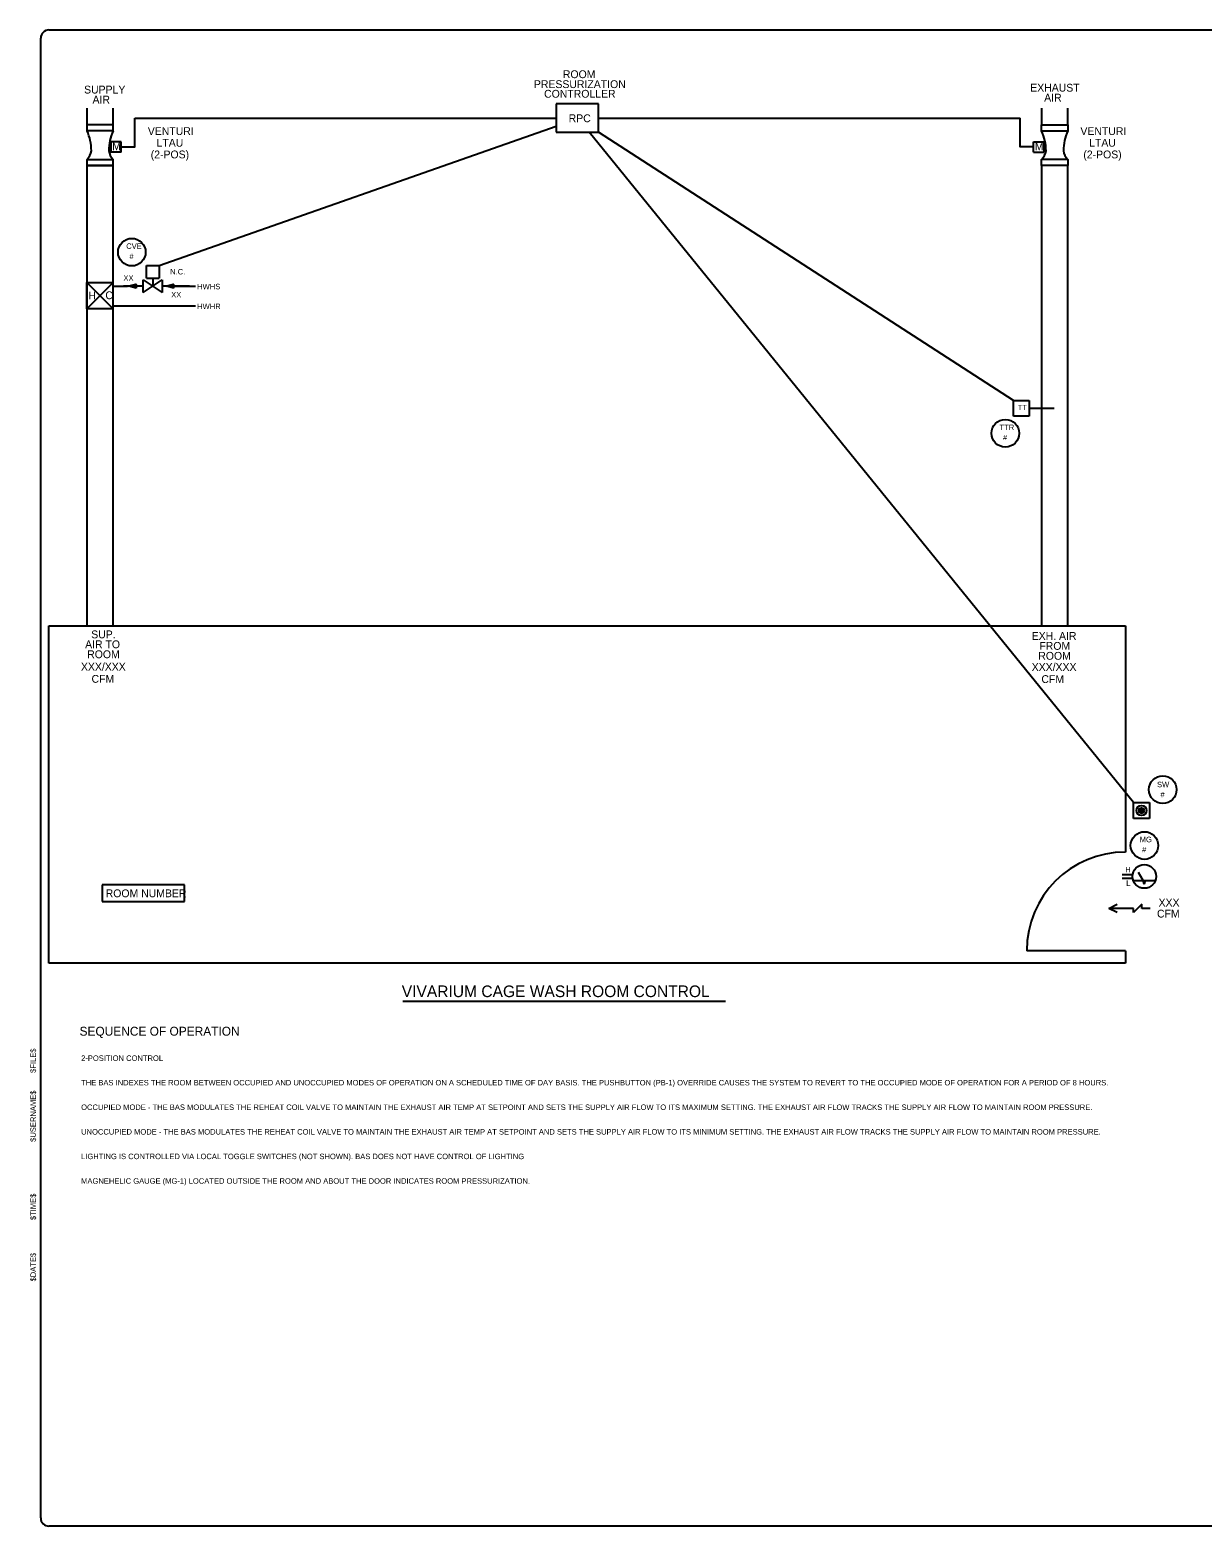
# Model space of a CAD drawing. Extents: x 0 to 567, y 1 to 184.
# Drawn here: x 289.6 to 432.3, y 1.7 to 183.7 of the extents above; entities that cross this region are included whole.
import ezdxf

# ---------------------------------------------------------------- set-up
doc = ezdxf.new("R2010")
doc.units = 0
for name, color, linetype in [('Default', 7, 'Continuous'), ('G-ANNO-CELL', 7, 'Continuous'), ('G-ANNO-NODE', 7, 'Continuous'), ('G-ANNO-TEXT', 7, 'Continuous'), ('G-ANNO-TTLB', 7, 'Continuous'), ('G-DETL-LINE', 7, 'Continuous'), ('G-DETL-TEXT', 7, 'Continuous')]:
    doc.layers.add(name, color=color, linetype=linetype)

msp = doc.modelspace()

# ---------------------------------------------------------------- linework, layer by layer
at = {"layer": 'G-ANNO-CELL'}
msp.add_line((334.98, 65.6), (374.27, 65.6), dxfattribs=at)
at = {"layer": 'G-ANNO-TTLB'}
for points in [[(290.92, 2.73), (290.92, 182.73)], [(291.92, 183.73), (535.67, 183.73)], [(535.67, 1.73), (291.92, 1.73)]]:
    msp.add_lwpolyline(points, dxfattribs=at)
for centre, start, end in [((291.92, 182.73), 90, 180), ((291.92, 2.73), 180, 270.0001)]:
    msp.add_arc(centre, 1, start, end, dxfattribs=at)
at = {"layer": 'G-DETL-LINE'}
for p, q in [((353.63, 174.74), (353.63, 171.28)), ((358.81, 174.74), (353.63, 174.74)), ((358.81, 171.28), (358.81, 174.74)), ((296.55, 174.23), (296.55, 172.17)), ((299.75, 172.17), (299.75, 174.23)), ((302.36, 173.01), (353.63, 173.01)), ((358.81, 173.01), (410.12, 173.01)), ((412.72, 174.23), (412.72, 172.17)), ((415.92, 172.17), (415.92, 174.23)), ((299.75, 171.44), (296.55, 171.44)), ((305.33, 155.06), (353.63, 172.03)), ((353.63, 171.28), (358.81, 171.28)), ((423.92, 89.74), (357.66, 171.28)), ((409.31, 138.65), (358.81, 171.28)), ((412.72, 171.44), (415.92, 171.44)), ((299.46, 170.14), (299.46, 168.86)), ((300.73, 170.14), (299.46, 170.14)), ((300.73, 168.86), (300.73, 170.14)), ((411.74, 170.14), (413.01, 170.14)), ((411.74, 168.86), (411.74, 170.14)), ((413.01, 170.14), (413.01, 168.86)), ((296.55, 167.98), (299.75, 167.98)), ((415.92, 167.98), (412.72, 167.98)), ((296.55, 167.24), (296.55, 111.23)), ((299.75, 167.24), (296.55, 167.24)), ((299.75, 111.23), (299.75, 167.24)), ((412.72, 167.24), (412.72, 111.23)), ((415.92, 111.23), (415.92, 167.24)), ((303.79, 153.52), (303.79, 155.06)), ((303.79, 155.06), (305.33, 155.06)), ((305.33, 155.06), (305.33, 153.52)), ((296.55, 149.8), (296.55, 153)), ((296.55, 153), (299.75, 153)), ((296.55, 153), (299.75, 149.8)), ((296.55, 149.8), (299.75, 153)), ((299.75, 149.8), (299.75, 153)), ((303.41, 151.79), (303.41, 153.33)), ((303.41, 153.33), (305.71, 151.79)), ((303.41, 151.79), (305.71, 153.33)), ((303.79, 153.52), (305.33, 153.52)), ((304.56, 153.52), (304.56, 152.56)), ((305.71, 153.33), (305.71, 151.79)), ((299.75, 152.56), (301.49, 152.56)), ((303.41, 152.56), (301, 152.56)), ((302.55, 152.56), (301.65, 152.56)), ((302.55, 152.6), (301.82, 152.6)), ((302.55, 152.52), (301.82, 152.52)), ((302.55, 152.64), (301.99, 152.64)), ((302.55, 152.48), (301.99, 152.48)), ((302.55, 152.68), (302.15, 152.68)), ((302.55, 152.44), (302.15, 152.44)), ((302.55, 152.72), (302.31, 152.72)), ((302.55, 152.4), (302.31, 152.4)), ((302.55, 152.76), (302.45, 152.76)), ((302.55, 152.36), (302.45, 152.36)), ((309.01, 152.56), (305.71, 152.56)), ((307.1, 152.56), (306.21, 152.56)), ((307.1, 152.6), (306.38, 152.6)), ((307.1, 152.52), (306.38, 152.52)), ((307.1, 152.64), (306.54, 152.64)), ((307.1, 152.48), (306.54, 152.48)), ((307.1, 152.68), (306.7, 152.68)), ((307.1, 152.44), (306.7, 152.44)), ((306.85, 152.56), (309.76, 152.56)), ((307.1, 152.72), (306.86, 152.72)), ((307.1, 152.4), (306.86, 152.4)), ((307.1, 152.76), (307.01, 152.76)), ((307.1, 152.36), (307.01, 152.36)), ((299.75, 149.8), (296.55, 149.8)), ((299.75, 150.16), (309.76, 150.16)), ((409.31, 138.65), (411.23, 138.65)), ((409.31, 136.73), (409.31, 138.65)), ((411.23, 138.65), (411.23, 136.73)), ((411.23, 136.73), (409.31, 136.73)), ((414.24, 137.69), (411.23, 137.69)), ((291.92, 111.23), (422.92, 111.23)), ((291.92, 70.23), (291.92, 111.23)), ((422.92, 111.23), (422.92, 83.73)), ((423.92, 89.74), (425.84, 89.74)), ((423.92, 87.82), (423.92, 89.74)), ((425.84, 89.74), (425.84, 87.82)), ((425.84, 87.82), (423.92, 87.82)), ((424.56, 88.72), (424.94, 89.1)), ((424.56, 88.77), (424.89, 89.1)), ((424.56, 88.83), (424.83, 89.1)), ((424.56, 88.8), (424.91, 88.45)), ((424.56, 88.74), (424.85, 88.45)), ((424.57, 88.85), (424.96, 88.46)), ((424.58, 88.67), (424.99, 89.08)), ((424.58, 88.89), (425, 88.47)), ((424.58, 88.67), (424.78, 88.47)), ((424.59, 88.63), (425.03, 89.07)), ((424.59, 88.91), (424.75, 89.07)), ((424.6, 88.93), (425.04, 88.49)), ((424.61, 88.6), (425.06, 89.05)), ((424.62, 88.97), (425.07, 88.51)), ((424.64, 88.56), (425.1, 89.02)), ((424.65, 89), (425.11, 88.54)), ((424.67, 88.54), (425.12, 88.99)), ((424.68, 89.02), (425.13, 88.57)), ((424.7, 88.51), (425.15, 88.96)), ((424.71, 89.05), (425.16, 88.6)), ((424.73, 88.49), (425.17, 88.93)), ((424.74, 89.07), (425.18, 88.63)), ((424.77, 88.47), (425.19, 88.89)), ((424.78, 89.08), (425.19, 88.68)), ((424.81, 88.46), (425.2, 88.85)), ((424.83, 89.1), (425.21, 88.72)), ((424.86, 88.45), (425.21, 88.8)), ((424.88, 89.1), (425.21, 88.77)), ((424.92, 88.45), (425.21, 88.74)), ((424.94, 89.1), (425.2, 88.83)), ((425, 88.47), (425.19, 88.66)), ((425.03, 89.07), (425.18, 88.92)), ((422.51, 81.01), (423.8, 81.01)), ((422.52, 80.53), (423.78, 80.53)), ((423.86, 80.28), (426.58, 80.28)), ((425.08, 80.28), (424.5, 81.24)), ((298.42, 79.73), (298.42, 77.73)), ((308.42, 79.73), (298.42, 79.73)), ((308.42, 77.73), (308.42, 79.73)), ((425.22, 80.04), (425.1, 80.04)), ((425.34, 80.04), (425.22, 80.04)), ((298.42, 77.73), (308.42, 77.73)), ((420.92, 76.88), (421.92, 77.38)), ((423.92, 76.88), (420.92, 76.88)), ((421.92, 76.38), (420.92, 76.88)), ((424.92, 77.38), (423.92, 76.38)), ((423.92, 76.38), (423.92, 76.88)), ((424.92, 76.88), (424.92, 77.38)), ((425.92, 76.88), (424.92, 76.88)), ((422.92, 71.73), (410.92, 71.73)), ((422.92, 71.73), (422.92, 70.23)), ((422.92, 70.23), (291.92, 70.23))]:
    msp.add_line(p, q, dxfattribs=at)
for points in [[(300.73, 169.5), (302.36, 169.5), (302.36, 173.01)], [(411.74, 169.5), (410.12, 169.5), (410.12, 173.01)], [(299.75, 171.44), (299.75, 172.17), (296.55, 172.17), (296.55, 171.44)], [(412.72, 171.44), (412.72, 172.17), (415.92, 172.17), (415.92, 171.44)], [(296.55, 167.98), (296.55, 167.24), (299.75, 167.24), (299.75, 167.98)], [(300.73, 168.86), (299.46, 168.86)], [(411.74, 168.86), (413.01, 168.86)], [(415.92, 167.98), (415.92, 167.24), (412.72, 167.24), (412.72, 167.98)], [(302.55, 152.33), (301.65, 152.56), (302.55, 152.78), (302.55, 152.33)], [(307.1, 152.33), (306.21, 152.56), (307.1, 152.78), (307.1, 152.33)]]:
    msp.add_lwpolyline(points, dxfattribs=at)
for centre, radius in [((424.88, 88.78), 0.617), ((424.88, 88.78), 0.325), ((425.22, 80.76), 1.44)]:
    msp.add_circle(centre, radius, dxfattribs=at)
for centre, radius, start, end in [((291.42, 169.04), 5.67, 0, 25.0576), ((304.88, 169.04), 5.67, 154.9424, 180), ((407.59, 169.04), 5.67, 0, 25.0576), ((421.05, 169.04), 5.67, 154.9424, 180), ((295.22, 169.31), 1.89, 315, 351.8699), ((301.08, 169.31), 1.89, 188.1301, 225), ((411.39, 169.31), 1.89, 315, 351.8699), ((417.25, 169.31), 1.89, 188.1301, 225), ((422.92, 71.73), 12, 90, 180), ((425.22, 80.04), 0.12, 0, 180), ((425.22, 80.04), 0.12, 180, 0)]:
    msp.add_arc(centre, radius, start, end, dxfattribs=at)
at = {"layer": 'G-DETL-TEXT'}
for centre in [(302.01, 156.7), (408.31, 134.67), (427.47, 91.32), (425.24, 84.52)]:
    msp.add_circle(centre, 1.68, dxfattribs=at)

# ---------------------------------------------------------------- texts
at = {"layer": 'Default'}
for s, p in [('TT', (409.83, 137.48)), ('#', (408.04, 133.84))]:
    msp.add_text(s, height=0.64, dxfattribs=at).set_placement(p)
at = {"layer": 'G-ANNO-CELL'}
for s, height, p in [('VIVARIUM CAGE WASH ROOM CONTROL', 1.4167, (334.86, 66.08)), ('SEQUENCE OF OPERATION', 1.0833, (295.65, 61.39))]:
    msp.add_text(s, height=height, dxfattribs=at).set_placement(p)
at = {"layer": 'G-ANNO-NODE'}
for s, p in [('$FILE$', (290.33, 56.86)), ('$USERNAME$', (290.33, 48.47)), ('$TIME$', (290.33, 38.95)), ('$DATE$', (290.33, 31.49))]:
    msp.add_text(s, height=0.667, rotation=90, dxfattribs=at).set_placement(p)
at = {"layer": 'G-ANNO-TEXT'}
for s, height, p in [('2-POSITION CONTROL', 0.6667, (295.84, 58.32)), ('THE BAS INDEXES THE ROOM BETWEEN OCCUPIED AND UNOCCUPIED MODES OF OPERATION ON A SCHEDULED TIME OF DAY BASIS. THE PUSHBUTTON (PB-1) OVERRIDE CAUSES THE SYSTEM TO REVERT TO THE OCCUPIED MODE OF OPERATION FOR A PERIOD OF 8 HOURS.', 0.66667, (295.84, 55.34)), ('OCCUPIED MODE - THE BAS MODULATES THE REHEAT COIL VALVE TO MAINTAIN THE EXHAUST AIR TEMP AT SETPOINT AND SETS THE SUPPLY AIR FLOW TO ITS MAXIMUM SETTING. THE EXHAUST AIR FLOW TRACKS THE SUPPLY AIR FLOW TO MAINTAIN ROOM PRESSURE.', 0.66667, (295.84, 52.35)), ('UNOCCUPIED MODE - THE BAS MODULATES THE REHEAT COIL VALVE TO MAINTAIN THE EXHAUST AIR TEMP AT SETPOINT AND SETS THE SUPPLY AIR FLOW TO ITS MINIMUM SETTING. THE EXHAUST AIR FLOW TRACKS THE SUPPLY AIR FLOW TO MAINTAIN ROOM PRESSURE.', 0.66667, (295.84, 49.36)), ('LIGHTING IS CONTROLLED VIA LOCAL TOGGLE SWITCHES (NOT SHOWN). BAS DOES NOT HAVE CONTROL OF LIGHTING', 0.6667, (295.84, 46.37)), ('MAGNEHELIC GAUGE (MG-1) LOCATED OUTSIDE THE ROOM AND ABOUT THE DOOR INDICATES ROOM PRESSURIZATION.', 0.6667, (295.84, 43.38))]:
    msp.add_text(s, height=height, dxfattribs=at).set_placement(p)
at = {"layer": 'G-DETL-LINE'}
for s, height, p in [('ROOM', 0.952, (354.47, 177.87)), ('SUPPLY', 0.952, (296.2, 176)), ('PRESSURIZATION', 0.9523, (350.94, 176.66)), ('EXHAUST', 0.952, (411.34, 176.23)), ('AIR', 0.952, (297.23, 174.78)), ('CONTROLLER', 0.952, (352.18, 175.49)), ('AIR', 0.952, (413.04, 175.02)), ('RPC', 0.952, (355.17, 172.51)), ('  VENTURI', 0.952, (303.25, 170.95)), ('  VENTURI', 0.952, (416.74, 170.95)), ('M', 0.952, (299.62, 169.1)), ('     LTAU', 0.952, (303.25, 169.53)), ('M', 0.952, (411.9, 169.1)), ('     LTAU', 0.952, (416.74, 169.53)), ('   (2-POS)', 0.952, (303.25, 168.11)), ('   (2-POS)', 0.952, (416.74, 168.11)), ('XX', 0.667, (300.99, 153.22)), ('N.C.', 0.667, (306.67, 153.99)), ('H', 0.952, (296.72, 150.95)), ('C', 0.952, (298.79, 150.98)), ('XX', 0.667, (306.8, 151.19)), ('HWHS', 0.667, (309.96, 152.18)), ('HWHR', 0.667, (309.96, 149.77)), ('AIR TO', 0.952, (296.33, 108.52)), ('SUP.', 0.952, (297.07, 109.73)), ('EXH. AIR', 0.952, (411.52, 109.54)), ('FROM', 0.952, (412.45, 108.33)), ('ROOM', 0.952, (296.58, 107.31)), ('ROOM', 0.952, (412.32, 107.12)), ('XXX/XXX', 0.952, (295.82, 105.8)), ('XXX/XXX', 0.952, (411.52, 105.76)), ('CFM', 0.952, (297.11, 104.32)), ('CFM', 0.952, (412.7, 104.29)), ('H', 0.667, (422.9, 81.24)), ('L', 0.667, (423.02, 79.6)), ('ROOM NUMBER', 0.9523, (298.83, 78.23)), ('CFM', 0.952, (426.77, 75.76)), ('XXX', 0.952, (426.96, 77.1))]:
    msp.add_text(s, height=height, dxfattribs=at).set_placement(p)
at = {"layer": 'G-DETL-TEXT'}
for s, p in [('CVE', (301.33, 157.1)), ('#', (301.72, 155.86)), ('TTR', (407.6, 135.06)), ('SW', (426.77, 91.61)), ('#', (427.18, 90.38)), ('MG', (424.66, 84.92)), ('#', (424.95, 83.68))]:
    msp.add_text(s, height=0.667, dxfattribs=at).set_placement(p)

doc.saveas('drawing.dxf')
